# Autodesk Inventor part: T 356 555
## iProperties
Company: Mayer & Müller AG Schaltgeräte
Created: 2005-10
Part Number: T 356 555
Material: 1.4301
Document SubType Name: Modeling
Designer: I.Baliuc
Manufacturer: Standard
Standards Organization: Custom
Description: Bolzen
Density: 7.86 g/cm^3
Author: T.Messerschmitt
Revision Number: 356555
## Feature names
1. Extrusion2
2. Extrusion3
3. Bohrung1 [Hole]
4. Fase1 [Chamfer]
5. Extrusion4
6. Fase2 [Chamfer]
